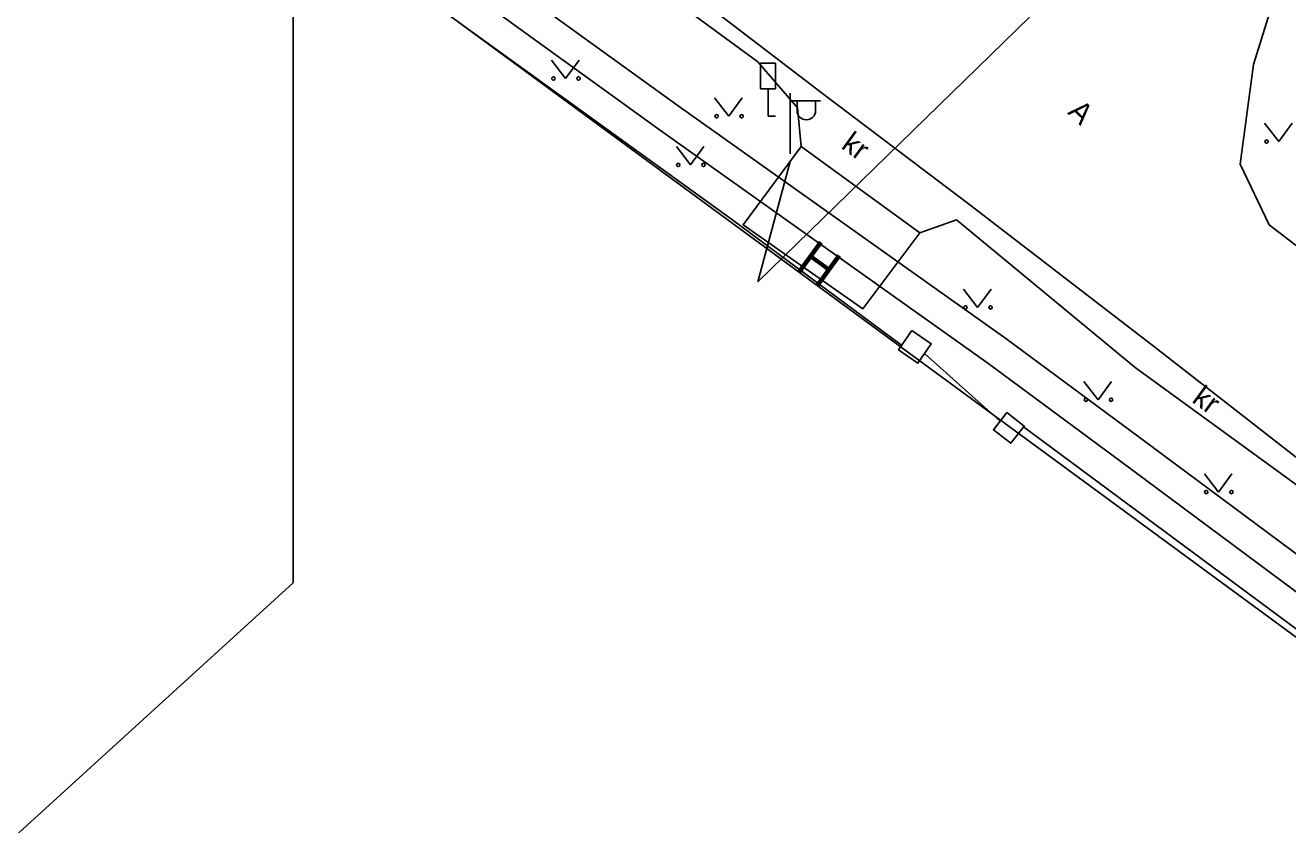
# Model space of a CAD drawing. Extents: x 554947 to 555436, y 6564938 to 6565792.
# Drawn here: x 555228.52 to 555270.11, y 6565557.19 to 6565583.53 of the extents above; entities that cross this region are included whole.
import ezdxf

# ---------------------------------------------------------------- set-up
doc = ezdxf.new("R2010")
doc.units = 0
for name, color, linetype in [('AED', 7, 'Continuous'), ('HALJASTUS', 7, 'Continuous'), ('HOONE', 7, 'Continuous'), ('KASUTUSALA', 7, 'Continuous'), ('LIIKLUS', 7, 'Continuous'), ('MPOHULIIN', 7, 'Continuous'), ('PIIR', 7, 'Continuous'), ('POST', 7, 'Continuous'), ('PR_SIDE', 7, 'Continuous'), ('TEE', 7, 'Continuous')]:
    doc.layers.add(name, color=color, linetype=linetype)

msp = doc.modelspace()

# ---------------------------------------------------------------- linework, layer by layer
at = {"layer": 'AED'}
msp.add_line((555258.145, 6565572.717), (555260.639, 6565570.489), dxfattribs=at)
for points in [[(555257.388, 6565572.989), (555251.782, 6565577.142), (555242.434, 6565583.901), (555242.233, 6565583.941), (555233.453, 6565584.321)], [(555301.646, 6565540.531), (555292.158, 6565547.42), (555274.134, 6565560.859), (555261.407, 6565570.297)]]:
    msp.add_lwpolyline(points, dxfattribs=at)
for points in [[(555257.729, 6565573.48), (555258.367, 6565573.036), (555257.924, 6565572.398), (555257.286, 6565572.842)], [(555260.862, 6565570.773), (555261.431, 6565570.327), (555260.985, 6565569.759), (555260.417, 6565570.205)]]:
    msp.add_lwpolyline(points, close=True, dxfattribs=at)
at = {"layer": 'HALJASTUS'}
for p, q in [((555245.859, 6565582.387), (555246.322, 6565581.78)), ((555246.322, 6565581.78), (555246.768, 6565582.387)), ((555251.23, 6565581.141), (555251.694, 6565580.534)), ((555251.694, 6565580.534), (555252.139, 6565581.141)), ((555269.351, 6565580.306), (555269.814, 6565579.699)), ((555269.814, 6565579.699), (555270.26, 6565580.306)), ((555249.97, 6565579.541), (555250.433, 6565578.934)), ((555250.433, 6565578.934), (555250.879, 6565579.541)), ((555259.431, 6565574.842), (555259.895, 6565574.235)), ((555259.895, 6565574.235), (555260.34, 6565574.842)), ((555263.398, 6565571.799), (555263.862, 6565571.192)), ((555263.862, 6565571.192), (555264.307, 6565571.799)), ((555267.366, 6565568.756), (555267.829, 6565568.149)), ((555267.829, 6565568.149), (555268.275, 6565568.756))]:
    msp.add_line(p, q, dxfattribs=at)
for centre in [(555245.921, 6565581.78), (555246.75, 6565581.78), (555251.293, 6565580.534), (555252.121, 6565580.534), (555269.413, 6565579.699), (555250.032, 6565578.934), (555250.861, 6565578.934), (555259.494, 6565574.235), (555260.322, 6565574.235), (555263.461, 6565571.192), (555264.29, 6565571.192), (555267.428, 6565568.149), (555268.257, 6565568.149)]:
    msp.add_circle(centre, 0.055, dxfattribs=at)
at = {"layer": 'HOONE'}
msp.add_lwpolyline([(555257.995, 6565576.697), (555256.108, 6565574.186), (555252.169, 6565576.961), (555254.087, 6565579.537), (555257.995, 6565576.697)], dxfattribs=at)
at = {"layer": 'KASUTUSALA'}
msp.add_lwpolyline([(555330.79, 6565520.761), (555305.197, 6565537.964), (555302.6, 6565539.71), (555242.37, 6565583.94), (555238.34, 6565585.593), (555238.34, 6565584.092), (555236.34, 6565584.168), (555236.34, 6565586.946), (555231.217, 6565605.702), (555233.309, 6565605.634), (555234.35, 6565605.6), (555235.803, 6565604.987), (555234.66, 6565604.12), (555233.701, 6565604.199), (555238.103, 6565588.08), (555238.175, 6565587.82), (555243.331, 6565585.721), (555250.029, 6565580.878), (555260.82, 6565573.213), (555265.213, 6565569.964), (555284.475, 6565555.644), (555289.407, 6565551.783), (555304.515, 6565541.003), (555310.277, 6565536.492)], dxfattribs=at)
at = {"layer": 'LIIKLUS'}
for p, q in [((555252.739, 6565582.29), (555252.739, 6565581.44)), ((555253.239, 6565582.29), (555252.739, 6565582.29)), ((555253.239, 6565582.29), (555253.239, 6565581.44)), ((555253.239, 6565581.44), (555252.739, 6565581.44)), ((555252.989, 6565581.44), (555252.989, 6565580.54)), ((555253.239, 6565580.54), (555252.989, 6565580.54))]:
    msp.add_line(p, q, dxfattribs=at)
at = {"layer": 'MPOHULIIN'}
msp.add_line((555253.72, 6565579.044), (555252.652, 6565575.082), dxfattribs=at)
msp.add_lwpolyline([(555252.652, 6565575.082), (555268.428, 6565590.453)], dxfattribs=at)
at = {"layer": 'PIIR'}
msp.add_lwpolyline([(555393.069, 6565560.972), (555353.12, 6565523.87), (555343.14, 6565512.46), (555302.6, 6565539.71), (555242.37, 6565583.94), (555179.42, 6565586.32), (555138.98, 6565580.6), (555121.18, 6565602.26), (555116.17, 6565610.5), (555109.96, 6565624.83), (555093.56, 6565628.47), (555079.04, 6565618.4), (555074.13, 6565607.82), (555075.34, 6565593.24), (555091.74, 6565551.94), (555171.91, 6565394.64), (555191.35, 6565341.19), (555195.08, 6565294.61), (555195.28, 6565271.63), (555191.64, 6565237.48)], dxfattribs=at)
msp.add_lwpolyline([(555121.18, 6565602.26), (555138.98, 6565580.6), (555179.42, 6565586.32), (555242.37, 6565583.94), (555302.6, 6565539.71), (555287.77, 6565518.56), (555207.29, 6565506.14), (555200.64, 6565496.23), (555185.97, 6565502.75), (555177.68, 6565506.44), (555171.49, 6565510.85), (555162.05, 6565514.45), (555140.65, 6565513.25), (555139.49, 6565523.98), (555139.26, 6565529.51), (555141.68, 6565537.52), (555139.64, 6565543.1), (555131.01, 6565550.06), (555126.35, 6565558.74), (555119.63, 6565564.84), (555105.26, 6565587.71), (555099.5, 6565594.91), (555116.17, 6565610.5)], close=True, dxfattribs=at)
at = {"layer": 'POST'}
for p, q in [((555253.72, 6565579.294), (555253.72, 6565581.294)), ((555253.72, 6565581.044), (555254.72, 6565581.044)), ((555253.946, 6565580.723), (555253.946, 6565581.044)), ((555254.559, 6565580.723), (555254.559, 6565581.044)), ((555253.72, 6565579.044), (555253.72, 6565579.044))]:
    msp.add_line(p, q, dxfattribs=at)
msp.add_arc((555254.253, 6565580.723), 0.306, 180, 0, dxfattribs=at)
at = {"layer": 'PR_SIDE'}
for points in [[(555309.355, 6565535.944), (555304.351, 6565539.861), (555303.916, 6565540.202), (555288.808, 6565550.982), (555283.868, 6565554.848), (555264.618, 6565569.161), (555260.234, 6565572.403), (555249.446, 6565580.065), (555242.843, 6565584.84), (555237.34, 6565587.08), (555232.399, 6565605.169), (555232.137, 6565606.132)], [(555237.34, 6565587.08), (555237.34, 6565565.16), (555226.585, 6565555.364), (555203.636, 6565543.731), (555203.636, 6565538.53), (555204.984, 6565533.828), (555204.645, 6565532.63)]]:
    msp.add_lwpolyline(points, dxfattribs=at)
at = {"layer": 'TEE'}
for points in [[(555309.906, 6565538.03), (555305.168, 6565541.808), (555305.066, 6565542.334), (555294.766, 6565550.531), (555276.823, 6565564.276), (555265.732, 6565572.927), (555259.684, 6565577.587), (555254.787, 6565581.289), (555247.931, 6565586.532), (555243.893, 6565589.125), (555239.934, 6565591.048), (555235.042, 6565592.642), (555234.652, 6565590.428), (555233.978, 6565588.723)], [(555254.087, 6565579.537), (555253.958, 6565580.81), (555252.655, 6565582.326), (555247.572, 6565586.061), (555243.345, 6565588.774), (555239.362, 6565590.351), (555234.652, 6565590.428)], [(555272.683, 6565590.134), (555271.484, 6565588.076), (555270.516, 6565586.416), (555269.723, 6565584.609), (555268.981, 6565582.24), (555268.55, 6565578.954), (555269.504, 6565576.952), (555281.044, 6565568.103), (555297.768, 6565555.508), (555316.66, 6565541.129), (555323.074, 6565536.252), (555328.036, 6565533.009), (555332.837, 6565530.879), (555337.611, 6565529.695), (555343.363, 6565529.946), (555348.456, 6565531.532), (555353.801, 6565534.677), (555358.561, 6565538.499)], [(555304.166, 6565537.744), (555304.47, 6565538.257), (555305.035, 6565540.465), (555305.168, 6565541.808), (555294.581, 6565550.293), (555276.533, 6565563.926), (555265.084, 6565572.259), (555259.201, 6565577.119), (555257.995, 6565576.697)]]:
    msp.add_lwpolyline(points, dxfattribs=at)

# ---------------------------------------------------------------- texts
at = {"layer": 'HOONE'}
msp.add_text('H', height=1.2, rotation=323.9607, dxfattribs=at).set_placement((555253.858, 6565575.537))
at = {"layer": 'TEE'}
for s, rotation, p in [('A', 316.1056, (555262.838, 6565580.641)), ('kr', 323.9607, (555255.366, 6565579.505)), ('kr', 323.9052, (555266.922, 6565571.139))]:
    msp.add_text(s, height=0.7, rotation=rotation, dxfattribs=at).set_placement(p)

doc.saveas('drawing.dxf')
